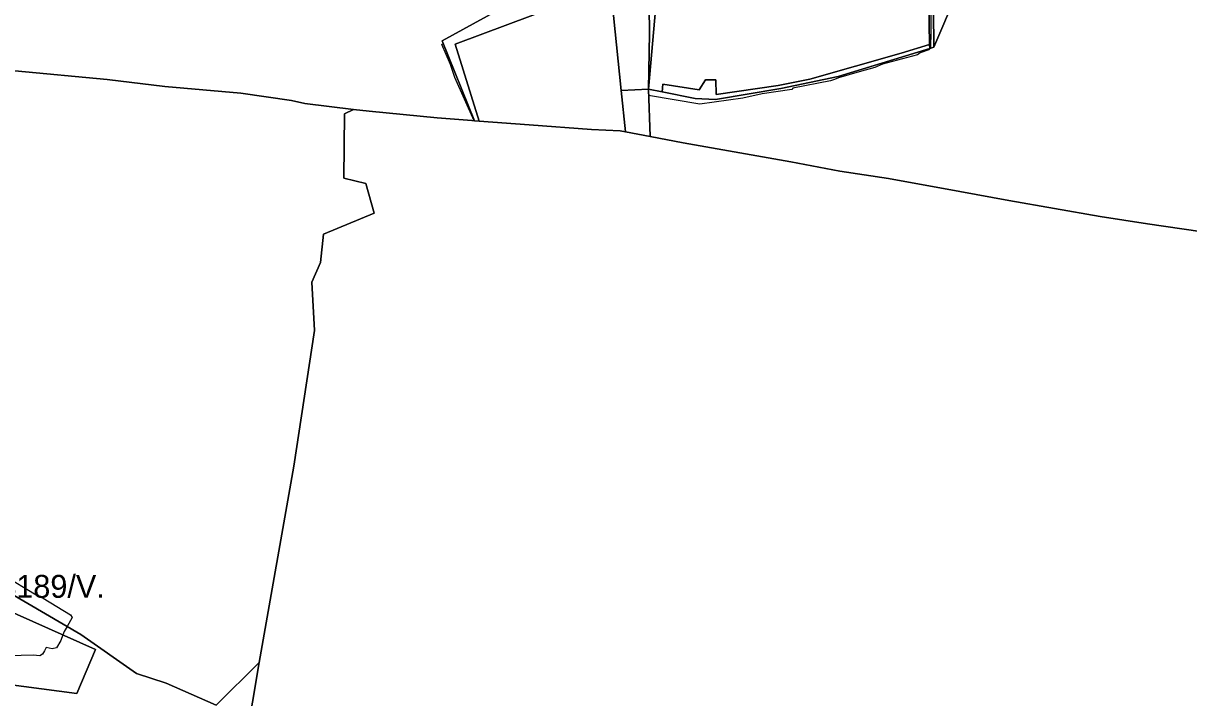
# Model space of a CAD drawing. Extents: x -477304 to -465429, y -1159113 to -1149210.
# Drawn here: x -473764 to -473001, y -1155534 to -1155092 of the extents above; entities that cross this region are included whole.
import ezdxf

# ---------------------------------------------------------------- set-up
doc = ezdxf.new("R2010")
doc.units = 0
for name, color, linetype in [('BPEJ_s', 7, 'Continuous'), ('PUPFL_s', 7, 'Continuous'), ('trav_porost_s', 7, 'Continuous')]:
    doc.layers.add(name, color=color, linetype=linetype)

msp = doc.modelspace()

# ---------------------------------------------------------------- linework, layer by layer
at = {"layer": 'BPEJ_s'}
for points in [[(-473170.31, -1155043.13), (-473169.88, -1155097.56), (-473170.09, -1155107.77), (-473170.47, -1155108.3), (-473171.16, -1155109.26), (-473176.9, -1155111.17), (-473178.6, -1155112.45), (-473201.57, -1155118.62), (-473206.67, -1155120.74), (-473216.81, -1155123.64), (-473230.48, -1155127.55), (-473233.1, -1155128.64), (-473235.59, -1155129.67), (-473260.25, -1155134.35), (-473260.89, -1155135.2), (-473280.24, -1155138.18), (-473293, -1155140.94), (-473321.07, -1155144.77), (-473354.67, -1155139.1), (-473353.67, -1155166.14), (-473355.1, -1155165.87), (-473373.26, -1155162.42), (-473392.03, -1155161.46), (-473432.75, -1155158.36), (-473468.65, -1155155.71), (-473468.89, -1155155.69), (-473481.61, -1155127.33), (-473484.37, -1155118.83), (-473490.12, -1155105.72), (-473489.05, -1155105.1), (-473489.74, -1155103.39), (-473390.35, -1155048.64)], [(-473170.31, -1155043.13), (-473169.88, -1155097.56), (-473170.09, -1155107.77), (-473170.47, -1155108.3), (-473171.16, -1155109.26), (-473176.9, -1155111.17), (-473178.6, -1155112.45), (-473201.57, -1155118.62), (-473206.67, -1155120.74), (-473216.81, -1155123.64), (-473230.48, -1155127.55), (-473233.1, -1155128.64), (-473235.59, -1155129.67), (-473260.25, -1155134.35), (-473260.89, -1155135.2), (-473280.24, -1155138.18), (-473293, -1155140.94), (-473321.07, -1155144.77), (-473354.67, -1155139.1), (-473353.67, -1155166.14), (-473355.1, -1155165.87)], [(-473355.1, -1155165.87), (-473373.26, -1155162.42), (-473392.03, -1155161.46), (-473432.75, -1155158.36), (-473468.65, -1155155.71), (-473468.89, -1155155.69), (-473481.61, -1155127.33), (-473484.37, -1155118.83), (-473490.12, -1155105.72), (-473489.05, -1155105.1), (-473489.74, -1155103.39), (-473390.35, -1155048.64)], [(-473778.24, -1155452.46), (-473754.42, -1155466.92), (-473751.02, -1155468.41), (-473733.16, -1155479.46), (-473731.88, -1155481.16), (-473735.3, -1155487.1), (-473737.13, -1155490.29), (-473737.99, -1155492.62), (-473739.33, -1155496.26), (-473742.3, -1155501.15), (-473745.07, -1155501.79), (-473748.89, -1155500.94), (-473750.08, -1155502.91), (-473751.45, -1155505.19), (-473753.15, -1155506.26), (-473757.4, -1155505.83), (-473788.87, -1155506.68)], [(-473778.24, -1155452.46), (-473754.42, -1155466.92), (-473751.02, -1155468.41), (-473733.16, -1155479.46), (-473731.88, -1155481.16), (-473735.3, -1155487.1), (-473737.13, -1155490.29), (-473737.99, -1155492.62), (-473739.33, -1155496.26), (-473742.3, -1155501.15), (-473745.07, -1155501.79), (-473748.89, -1155500.94), (-473750.08, -1155502.91), (-473751.45, -1155505.19), (-473753.15, -1155506.26), (-473757.4, -1155505.83), (-473788.87, -1155506.68)]]:
    msp.add_lwpolyline(points, dxfattribs=at)
at = {"layer": 'PUPFL_s'}
for points in [[(-473261.67, -1155182.7), (-473332.13, -1155170.24), (-473353.67, -1155166.14), (-473354.82, -1155135.11), (-473345.7, -1155136.78), (-473324.3, -1155141.25), (-473310.8, -1155141.72), (-473268.06, -1155134.61), (-473230.58, -1155126.8), (-473170.66, -1155108.36), (-473168.03, -1155107.51), (-473093.82, -1154933.76), (-473067.01, -1154904.59), (-473033.72, -1154939.88), (-472801.98, -1154920.79)], [(-473093.82, -1154933.76), (-473168.03, -1155107.51), (-473168.97, -1154989.09)], [(-473390.35, -1155048.64), (-473489.74, -1155103.39), (-473468.65, -1155155.71), (-473470.36, -1155155.57), (-473493.08, -1155153.74), (-473537.63, -1155149.54), (-473547.8, -1155148.31), (-473579.69, -1155144.48), (-473588.49, -1155142.49), (-473621.67, -1155137.59), (-473671.35, -1155133.39), (-473709.16, -1155128.63), (-473769.57, -1155123.1), (-473826.55, -1155115.89), (-473787.7, -1154943.82)], [(-473769.57, -1155123.1), (-473709.16, -1155128.63), (-473671.35, -1155133.39), (-473621.67, -1155137.59), (-473588.49, -1155142.49), (-473579.69, -1155144.48), (-473547.8, -1155148.31), (-473553.78, -1155151.17), (-473554.14, -1155193.25), (-473539.79, -1155196.77), (-473534.29, -1155216.22), (-473567.38, -1155230.02), (-473569.44, -1155248.66), (-473575.06, -1155261.55), (-473573.27, -1155293.08), (-473586.94, -1155381.95), (-473609.64, -1155510.66), (-473637.69, -1155538.72), (-473670.48, -1155524.15), (-473689.77, -1155517.83), (-473726.26, -1155492.39), (-473816.42, -1155439.69)], [(-473631.01, -1155637.9), (-473609.64, -1155510.66), (-473586.94, -1155381.95), (-473573.27, -1155293.08), (-473575.06, -1155261.55), (-473569.44, -1155248.66), (-473567.38, -1155230.02), (-473534.29, -1155216.22), (-473539.79, -1155196.77), (-473554.14, -1155193.25), (-473553.78, -1155151.17), (-473547.8, -1155148.31), (-473537.63, -1155149.54), (-473493.08, -1155153.74), (-473470.36, -1155155.57), (-473468.65, -1155155.71), (-473465.62, -1155155.93), (-473432.75, -1155158.36), (-473392.03, -1155161.46), (-473373.26, -1155162.42), (-473369.77, -1155163.08), (-473353.67, -1155166.14), (-473332.13, -1155170.24), (-473261.67, -1155182.7), (-473229.59, -1155188.72), (-473197.58, -1155193.45), (-473151.07, -1155202.18), (-473118.88, -1155207.92), (-473059.11, -1155218.38), (-473028.17, -1155223.24), (-472993.69, -1155228.38)], [(-472993.69, -1155228.38), (-473028.17, -1155223.24), (-473059.11, -1155218.38), (-473118.88, -1155207.92), (-473151.07, -1155202.18), (-473197.58, -1155193.45), (-473229.59, -1155188.72), (-473261.67, -1155182.7)], [(-473816.42, -1155439.69), (-473726.26, -1155492.39), (-473689.77, -1155517.83), (-473670.48, -1155524.15), (-473637.69, -1155538.72), (-473609.64, -1155510.66), (-473631.01, -1155637.9), (-473633.67, -1155635.53), (-473638.65, -1155611.57), (-473650.45, -1155550.93), (-473736.85, -1155560.83), (-473761.38, -1155552.4), (-473778.92, -1155543.45)]]:
    msp.add_lwpolyline(points, dxfattribs=at)
for points in [[(-473170.66, -1155108.36), (-473170.85, -1155105.72), (-473172.54, -1154996.43), (-473224.27, -1155002.26), (-473168.97, -1154989.09), (-473168.03, -1155107.51)], [(-473170.85, -1155105.72), (-473170.66, -1155108.36), (-473230.58, -1155126.8), (-473268.06, -1155134.61), (-473310.8, -1155141.72), (-473324.3, -1155141.25), (-473345.7, -1155136.78), (-473345.46, -1155131.79), (-473321.48, -1155135.41), (-473317.34, -1155128.87), (-473310.62, -1155129.01), (-473310.38, -1155138.61), (-473269.8, -1155132.59), (-473249.1, -1155128.5), (-473189.38, -1155111.37)], [(-473829.95, -1155517.71), (-473728.99, -1155531.01), (-473716.68, -1155502.1), (-473819.45, -1155456.37)], [(-473819.45, -1155456.37), (-473716.68, -1155502.1), (-473728.99, -1155531.01), (-473829.95, -1155517.71)]]:
    msp.add_lwpolyline(points, close=True, dxfattribs=at)
at = {"layer": 'trav_porost_s'}
for points in [[(-473263.14, -1155021.92), (-473172.54, -1154996.43), (-473170.85, -1155105.72), (-473189.38, -1155111.37), (-473249.1, -1155128.5), (-473269.8, -1155132.59), (-473310.38, -1155138.61), (-473310.62, -1155129.01), (-473317.34, -1155128.87), (-473321.48, -1155135.41), (-473345.46, -1155131.79), (-473345.7, -1155136.78), (-473354.82, -1155135.11), (-473350.03, -1155080.69), (-473325.91, -1155078.7), (-473250.52, -1155085.6)], [(-473390.35, -1155048.64), (-473377.43, -1155047.9), (-473376.11, -1155064.37), (-473362.79, -1155063.71), (-473362.77, -1155066.06), (-473379.59, -1155067.41), (-473481.31, -1155105.45), (-473465.62, -1155155.93), (-473468.65, -1155155.71), (-473489.74, -1155103.39)], [(-473432.75, -1155158.36), (-473465.62, -1155155.93), (-473481.31, -1155105.45), (-473379.59, -1155067.41), (-473372.57, -1155135.85), (-473369.77, -1155163.08), (-473373.26, -1155162.42), (-473392.03, -1155161.46)], [(-473354.07, -1155098.6), (-473354.82, -1155135.11), (-473372.57, -1155135.85), (-473379.59, -1155067.41), (-473362.77, -1155066.06), (-473362.65, -1155081.62), (-473354.31, -1155080.93)], [(-473354.31, -1155080.93), (-473350.03, -1155080.69), (-473354.82, -1155135.11), (-473354.07, -1155098.6)], [(-473372.57, -1155135.85), (-473354.82, -1155135.11), (-473353.67, -1155166.14), (-473369.77, -1155163.08)]]:
    msp.add_lwpolyline(points, close=True, dxfattribs=at)

# ---------------------------------------------------------------- texts
at = {"layer": 'BPEJ_s'}
msp.add_text('84189/V.', height=15, dxfattribs=at).set_placement((-473790.88, -1155468.28))

doc.saveas('drawing.dxf')
